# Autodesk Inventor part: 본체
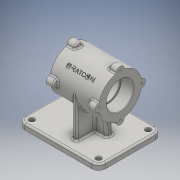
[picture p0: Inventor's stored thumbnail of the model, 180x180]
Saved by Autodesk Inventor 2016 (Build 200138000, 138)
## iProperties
Created: 2015-12
Part Number: 본체
Material: Generic
Document SubType Name: Modeling
Designer: Administrator
Density: 1 g/cm^3
Appearance: Default
Author: Administrator
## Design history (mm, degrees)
sketch "스케치1"
  geometry: L1 (-70, 55)-(70, 55); L2 (70, 55)-(70, -55); L3 (70, -55)-(-70, -55); L4 (-70, -55)-(-70, 55); 3 further points
  constraints: 8 end point, 2 midpoint, 2 parallel, 1 horizontal, 1 horizontal alignment, 1 perpendicular, 1 vertical alignment
  dimensions: "d0" = 140 distance of L1.start L1.end; "d1" = 110 distance of L1.end L2.end
extrude "돌출1" new body sketch "스케치1" distance "d2" = 10; taper "d3" = 0 deg
node "작업 평면1"
sketch "스케치2"
  geometry: C1 r 37 at (-80, 55); 1 further point
  constraints: 1 centre point, 1 horizontal alignment
  dimensions: "d5" = 74 diameter of C1; "d6" = 80 distance of point (0, 55) C1.centre
extrude "돌출2" join sketch "스케치2" distance "d7" = 85; taper "d8" = 0 deg
sketch "스케치5"
  geometry: L1 (-6, -37)-(-14, -37); L2 (-14, -37)-(-14, 37); L3 (-14, 37)-(-6, 37); L4 (-6, 37)-(-6, -37); L5 (70, 55)-(70, -55) reference; L6 (70, -55)-(-70, -55) reference; 4 further points
  constraints: 8 end point, 3 midpoint, 2 parallel, 1 horizontal, 1 horizontal alignment, 1 perpendicular
  dimensions: "d14" = 8 distance of L1.start L1.end; "d15" = 80 distance from line of point (-10, -37) L5; "d17" = 74 distance of L1.end L2.end
extrude "돌출3" join sketch "스케치5" distance "d18" = 70; taper "d19" = 0 deg
sketch "스케치6"
  geometry: L1 (-32.5, 43)-(52.5, 43) reference; L2 (-70, 0)-(70, 0) reference; L3 (-70, 0)-(-70, 10) reference; L4 (70, 10)-(-70, 10) reference; L5 (70, 0)-(70, 10) reference; L6 (-10.948, 43)-(-15, 10); L7 (30.948, 43)-(35, 10); L8 (-15, 10)-(35, 10); L9 (6, 10)-(14, 10) reference; L10 (6, 10)-(6, 80) reference; L11 (6, 80)-(14, 80) reference; L12 (14, 10)-(14, 80) reference; L13 (10, 10)-(10, 20.689); L14 (-10.948, 43)-(-10.101, 49.901); L15 (-10.101, 49.901)-(30.101, 49.901); L16 (30.101, 49.901)-(30.948, 43); 1 further point
  constraints: 14 end point, 4 point on line, 1 collinear, 1 horizontal, 1 midpoint, 1 vertical
  dimensions: "d20" = 97 deg angle of L4 L6; "d21" = 97 deg angle of L4 L7; "d22" = 25 distance of L13.start L6.end; "d23" = 50 distance of L7.end L6.end; "d25" = 6.9005 distance between parallel lines of L1 L15; "d26" = 97 deg angle of L1 L16; "d48" = 97 deg angle of L14 L1
extrude "돌출4" join sketch "스케치6" stored distance "d27" = 12; taper "d28" = 0 deg
sketch "스케치11"
  geometry: L1 (-32.5, 43)-(-32.5, 43) reference; L2 (52.5, 43)-(52.5, 117) reference; L3 (-56.347, 80)-(69.729, 80); L4 (-32.5, 103.5)-(-10.8, 103.5); L5 (-10.5, 103.2)-(-10.5, 101); L6 (-10.5, 101)-(30.5, 101); L7 (30.5, 101)-(30.5, 103.2); L8 (30.8, 103.5)-(52.5, 103.5); L9 (52.5, 103.5)-(52.5, 80); L10 (52.5, 80)-(-32.5, 80); L11 (-32.5, 103.5)-(-32.5, 80); A1 r 0.3 centre (-10.8, 103.2) between (-10.5, 103.2) and (-10.8, 103.5); A2 r 0.3 centre (30.8, 103.2) between (30.8, 103.5) and (30.5, 103.2); 3 further points
  constraints: 18 end point, 8 point on line, 5 perpendicular, 4 point on circle, 4 tangent, 2 centre point, 2 horizontal, 2 midpoint, 1 equal radius, 1 horizontal alignment
  dimensions: "d38" = 47 diameter of L4 L3; "d39" = 42 diameter of L6 L3; "d40" = 41 distance between parallel lines of L7 L5; "d41" = 22 distance between parallel lines of L2 L7; "d42" = 0.3 radius of A1
revolve "회전1" sketch "스케치11" stored, may be unused: angle "d43" = 90 deg
chamfer "모따기1" distance "d44" = 1; stored, may be unused: second distance "d45" = 2, angle "d46" = 45 deg
fillet "모깎기2" dims "d49" = 4
fillet "모깎기3" dims "d50" = 3
fillet "모깎기4" dims "d51" = 12
fillet "모깎기5" dims "d52" = 3
sketch "스케치12"
  geometry: L1 (58, 55)-(-58, 55) reference; L2 (70, -43)-(70, 43) reference; L3 (17.5, 0)-(-52.5, 0) reference; L4 (70, 43)-(70, -43) reference; L5 (58, -55)-(-58, -55) reference; L6 (-70, -43)-(-70, 43) reference; L7 (-58, 55)-(58, 55) reference; C1 r 4 at (-58, 43); C2 r 4 at (-58, -43); C3 r 4 at (58, 43); C4 r 4 at (58, -43); A1 r 12 centre (58, 43) between (70, 43) and (58, 55) reference; A2 r 12 centre (58, -43) between (58, -55) and (70, -43) reference; A3 r 12 centre (-58, -43) between (-70, -43) and (-58, -55) reference; A4 r 12 centre (-58, 43) between (-58, 55) and (-70, 43) reference; 1 further point
  constraints: 4 centre point, 2 vertical alignment, 1 horizontal alignment
  dimensions: "d53" = 8 diameter of C1; "d54" = 8 diameter of C2; "d55" = 8 diameter of C3; "d56" = 8 diameter of C4; "d58" = 12 distance from line of C3.centre L1; "d59" = 43 vertical distance of point (0, 0) C1.centre; "d60" = 86 distance of C2.centre C1.centre; "d61" = 12 distance from line of L6 C1.centre; "d62" = 116 distance of C3.centre C1.centre
extrude "돌출6" cut sketch "스케치12" stored distance "d63" = 15; taper "d64" = 0 deg
chamfer "모따기2" distance "d65" = 1; stored, may be unused: second distance "d66" = 2, angle "d67" = 45 deg
node "작업 평면6"
  node "작업 평면4"
  node "작업 평면5"
sketch "스케치18" dims "d65" = 1
  geometry: L1 (0, 37)-(85, 37) reference; L2 (96.815, 37)-(59.527, 37); L3 (85, 37)-(85, 44); L4 (85, 44)-(72.548, 44); L5 (72.548, 44)-(70, 37); L6 (85, -37)-(85, 37) reference; L7 (70, 37)-(85, 37); 1 further point
  constraints: 10 end point, 3 point on line, 1 horizontal, 1 perpendicular, 1 vertical
  dimensions: "d88" = 110 deg angle of L1 L5; "d89" = 14 diameter of L4 L2; "d90" = 15 distance of L1.end L5.end
revolve "회전2" sketch "스케치18" stored, may be unused: angle "d91" = 90 deg
sketch "스케치19"
  geometry: L1 (84, 23.5)-(84, -23.5) reference; L2 (84, 0)-(109.74, 0); 1 further point
  constraints: 2 end point, 1 horizontal, 1 midpoint
node "작업 평면7"
sketch "스케치20"
  geometry: C1 r 24.5 at (80, 55) reference; A1 r 37 centre (80, 55) between (73.031, 91.338) and (43.662, 61.969) reference; A2 r 7 centre (43, 55) between (43.662, 61.969) and (43.662, 48.031) reference; A3 r 37 centre (80, 55) between (43.662, 48.031) and (73.031, 18.662) reference; A4 r 7 centre (80, 18) between (73.031, 18.662) and (86.969, 18.662) reference; A5 r 37 centre (80, 55) between (86.969, 18.662) and (116.338, 48.031) reference; A6 r 7 centre (117, 55) between (116.338, 48.031) and (116.338, 61.969) reference; A7 r 37 centre (80, 55) between (116.338, 61.969) and (86.969, 91.338) reference; A8 r 7 centre (80, 92) between (86.969, 91.338) and (73.031, 91.338) reference; 5 further points
  constraints: 4 coincident
hole "구멍2" sketch "스케치20" at (117, 55), (80, 92), (80, 18), (43, 55) diameter "d95" = 3.242; stored, may be unused: countersink angle "d99" = 90 deg, drill point angle "d101" = 118 deg; dims "d96" = 9, "d97" = 4, "d98" = 2, "d100" = 11
fillet "모깎기8" dims "d102" = 3
fillet "모깎기9" dims "d103" = 3
sketch "스케치21"
  geometry: L1 (0, 0)-(0, 70.031); L2 (0, 0)-(-38.77, 38.77); C1 r 1.621 at (0, -37) reference; C2 r 1.621 at (-37, 0) reference; C3 r 1.621 at (0, 37) reference; C4 r 1.621 at (37, 0) reference; C5 r 24.5 at (0, 0) reference; A1 r 3 centre (-38.77, 9.842) between (-38.239, 6.889) and (-35.862, 9.104) reference; A2 r 7 centre (-37, 0) between (-38.239, 6.889) and (-38.239, -6.889) reference; A3 r 3 centre (-38.77, -9.842) between (-35.862, -9.104) and (-38.239, -6.889) reference; A4 r 37 centre (0, 0) between (-35.862, -9.104) and (-9.104, -35.863) reference; A5 r 3 centre (-9.842, -38.77) between (-6.889, -38.239) and (-9.104, -35.863) reference; A6 r 7 centre (0, -37) between (-6.889, -38.239) and (6.889, -38.239) reference; A7 r 3 centre (9.842, -38.77) between (9.104, -35.863) and (6.889, -38.239) reference; A8 r 37 centre (0, 0) between (9.104, -35.863) and (35.863, -9.104) reference; A9 r 3 centre (38.77, -9.842) between (38.239, -6.889) and (35.863, -9.104) reference; A10 r 7 centre (37, 0) between (38.239, -6.889) and (38.239, 6.889) reference; A11 r 3 centre (38.77, 9.842) between (35.863, 9.104) and (38.239, 6.889) reference; A12 r 37 centre (0, 0) between (35.863, 9.104) and (9.104, 35.863) reference; A13 r 3 centre (9.842, 38.77) between (6.889, 38.239) and (9.104, 35.863) reference; A14 r 7 centre (0, 37) between (6.889, 38.239) and (-6.889, 38.239) reference; A15 r 3 centre (-9.842, 38.77) between (-9.104, 35.863) and (-6.889, 38.239) reference; A16 r 37 centre (0, 0) between (-9.104, 35.863) and (-35.862, 9.104) reference; A17 r 37 centre (0, 0) between (-9.104, 35.863) and (-35.862, 9.104) reference; 2 further points
  constraints: 4 end point, 1 point on circle, 1 point on line, 1 vertical
  dimensions: "d104" = 45 deg angle of L1 L2
  node "투영된 루프10"
node "작업 평면8"
sketch "스케치22"
  geometry: L1 (-42.5, 37)-(42.5, 37) reference; L2 (-42.5, -18.921)-(-42.5, 18.921) reference; 4 further points
  constraints: 2 midpoint, 1 horizontal alignment, 1 vertical alignment, 1 other
feature "엠보싱2" sketch "스케치22" dims "d0" = 140, "d1" = 110, "d15" = 80, "d105" = 0.5, "d106" = 0
node "솔리드1"
pattern_circular "원형 패턴1" dims angle "d93" = 360 deg
mirror "대칭3"
mirror "대칭4"
node "투영된 루프2"
node "투영된 루프3"
node "투영된 루프6"
node "투영된 루프9"
other parameters: "d4" = -37.5
